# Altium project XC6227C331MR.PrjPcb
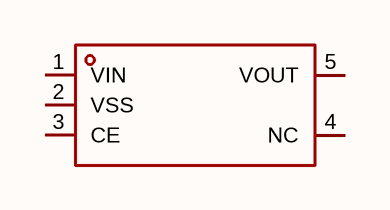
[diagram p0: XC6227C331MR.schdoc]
1 sheet, 1 parts. Net scope: global (net labels, ports and power ports of the same name join across sheets).

## Sheet XC6227C331MR.schdoc
size 127 x 101 mm

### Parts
U?  xc6227c331mr  [SOT-23-5_L2.9-W1.6-P0.95-LS2.8-BR]  (value not drawn)

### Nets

Not connected (* = marked no-connect by the designer): U? 1(VIN) 2(VSS) 3(CE) 4(NC) 5(VOUT)

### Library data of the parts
U? = xc6227c331mr: 输出极性:正极;工作电压:6V;输出电压:3.3V;输出电流:700mA;电源纹波抑制比(PSRR):65dB@(1kHz);输出类型:固定;; Manufacturer: TECH PUBLIC(台舟); AddInBom: yes; ModelId: 7ba65df16e7b4570af156e925f9c37fe; ModelTransform: 114.173,114.173,0,90,0,0,0,0,0; Output Configuration: 正极; Voltage - Supply: 6V; Output Voltage: 3.3V; Output Current: 700mA; Voltage Dropout: 160mV@(100mA); standby current: 100uA; Output Type: 固定; Number of Outputs: 1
